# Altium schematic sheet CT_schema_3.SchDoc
size 276 x 169 mm
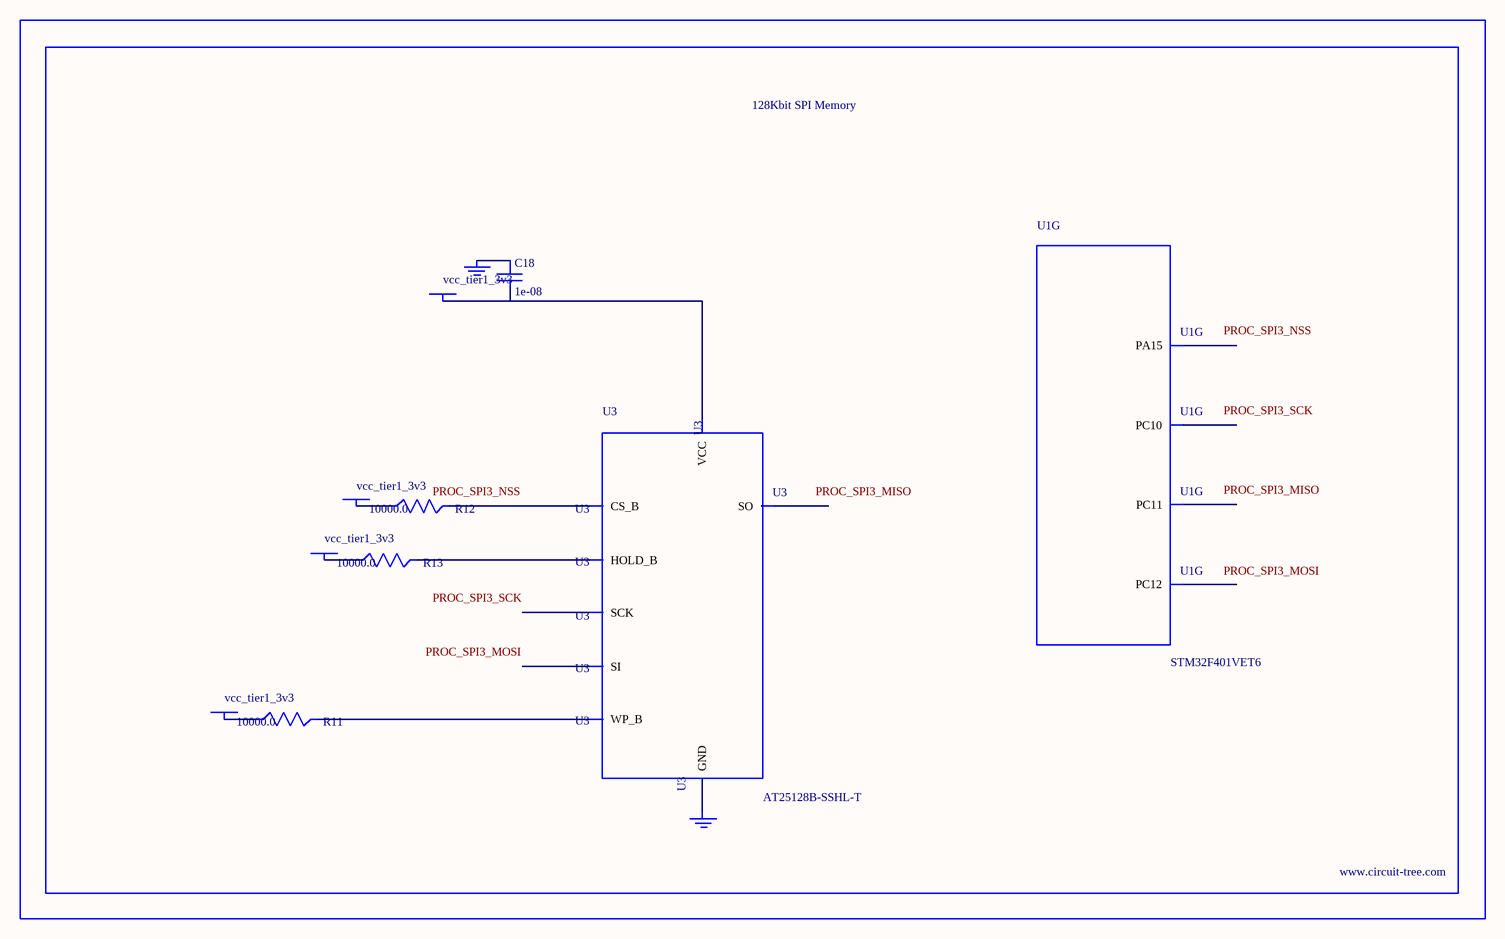
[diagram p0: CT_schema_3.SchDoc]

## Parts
BORDER2  (no value)
C18  1e-08  [C0402]
GND_INSTANCE_2_0  (no value)
GND_INSTANCE_2_1  (no value)
POWER_INSTANCE_2_0  vcc_tier1_3v3
POWER_INSTANCE_2_1  vcc_tier1_3v3
POWER_INSTANCE_2_2  vcc_tier1_3v3
POWER_INSTANCE_2_3  vcc_tier1_3v3
R11  10000.0  [R0603]
R12  10000.0  [R0603]
R13  10000.0  [R0603]
U1  STM32F401VET6  [LQFP100]  (part G of 10)
U3  AT25128B-SSHL-T  [SOIC-8]

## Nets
NetC18_1: C18.1 GND_INSTANCE_2_0.0(GND)
NetC18_2: C18.2 POWER_INSTANCE_2_3.0(PWR) U3.8(VCC)
NetGND_INSTANCE_2_1_0: GND_INSTANCE_2_1.0(GND) U3.4(GND)
NetPOWER_INSTANCE_2_0_0: POWER_INSTANCE_2_0.0(PWR) R12.1
NetPOWER_INSTANCE_2_1_0: POWER_INSTANCE_2_1.0(PWR) R11.1
NetPOWER_INSTANCE_2_2_0: POWER_INSTANCE_2_2.0(PWR) R13.1
NetR11_2: R11.2 U3.3(WP_B)
NetR12_2: R12.2 U3.1(CS_B)
NetR13_2: R13.2 U3.7(HOLD_B)

Not connected (* = marked no-connect by the designer): U1 77(PA15) 78(PC10) 79(PC11) 80(PC12); U3 2(SO) 5(SI) 6(SCK)

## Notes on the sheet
- Labels drawn without touching a wire or pin: PROC_SPI3_MISO, PROC_SPI3_MOSI, PROC_SPI3_NSS, PROC_SPI3_SCK

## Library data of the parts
BORDER2 = BORDER_PAGE2
C18 = C0402C103K3RAC
GND_INSTANCE_2_0 GND_INSTANCE_2_1 = GND
POWER_INSTANCE_2_0-POWER_INSTANCE_2_3 = PWR
R11-R13 = RC0603JR-0710KL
